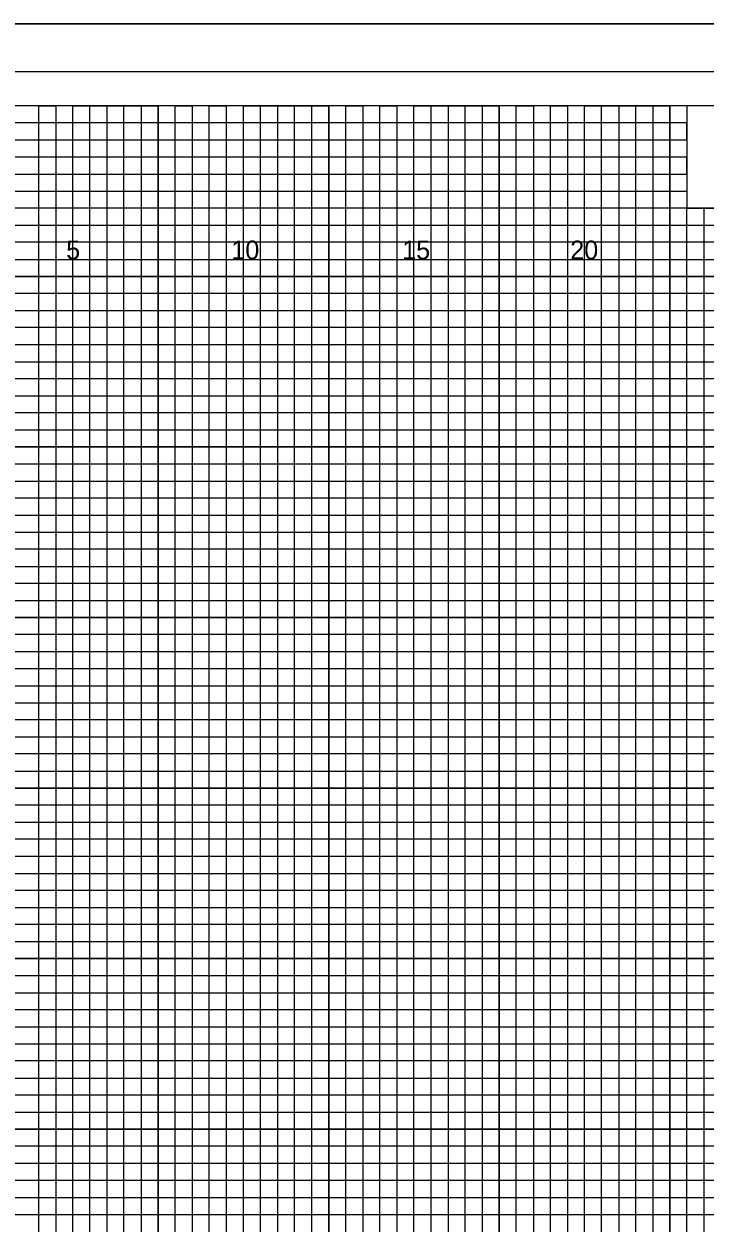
# Model space of a CAD drawing. Extents: x -4 to 103, y -2 to 209.
# Drawn here: x 54.82 to 74.78, y 32.25 to 67.4 of the extents above; entities that cross this region are included whole.
import ezdxf

# ---------------------------------------------------------------- set-up
doc = ezdxf.new("R2010")
doc.units = 0
for name, color, linetype in [('Exist XS Ground Line', 7, 'Continuous'), ('Old_Level_10', 7, 'Continuous'), ('Old_Level_16', 7, 'Continuous'), ('Old_Level_3', 7, 'Continuous'), ('Old_Level_5', 7, 'Continuous'), ('Old_Level_8', 7, 'Continuous'), ('Prop XS Finish Grade Earthwork', 7, 'Continuous'), ('Prop XS SE Text', 7, 'Continuous')]:
    doc.layers.add(name, color=color, linetype=linetype)

msp = doc.modelspace()

# ---------------------------------------------------------------- linework, layer by layer
at = {"layer": 'Exist XS Ground Line'}
msp.add_lwpolyline([(103, 66), (-2.8, 66), (-2.8, -1), (103, -1)], close=True, dxfattribs=at)
at = {"layer": 'Old_Level_10'}
for p, q in [((56.25, 0), (56.25, 65)), ((58.75, 0), (58.75, 65)), ((61.25, 0), (61.25, 65)), ((63.75, 0), (63.75, 65)), ((66.25, 0), (66.25, 65)), ((68.75, 0), (68.75, 65)), ((71.25, 0), (71.25, 65)), ((73.75, 0), (73.75, 65)), ((0, 62.5), (74.25, 62.5)), ((0, 60), (102.5, 60)), ((0, 57.5), (102.5, 57.5)), ((0, 55), (102.5, 55)), ((0, 52.5), (102.5, 52.5)), ((0, 50), (102.5, 50)), ((0, 47.5), (102.5, 47.5)), ((0, 45), (102.5, 45)), ((0, 42.5), (102.5, 42.5)), ((0, 40), (102.5, 40)), ((0, 37.5), (102.5, 37.5)), ((0, 35), (102.5, 35)), ((0, 32.5), (102.5, 32.5))]:
    msp.add_line(p, q, dxfattribs=at)
at = {"layer": 'Old_Level_3'}
msp.add_line((-3.5, 67.4), (103.4, 67.4), dxfattribs=at)
at = {"layer": 'Old_Level_5'}
msp.add_lwpolyline([(103.4, 67.4), (-3.5, 67.4), (-3.5, -2.425), (103.4, -2.425)], close=True, dxfattribs=at)
at = {"layer": 'Old_Level_8'}
for points in [[(56.25, 0), (56.25, 65), (58.75, 65), (58.75, 0)], [(61.25, 0), (61.25, 65), (63.75, 65), (63.75, 0)], [(66.25, 0), (66.25, 65), (68.75, 65), (68.75, 0)], [(71.25, 0), (71.25, 65), (73.75, 65), (73.75, 0)], [(0, 62.5), (74.25, 62.5)], [(0, 57.5), (102.5, 57.5), (102.5, 60), (0, 60)], [(0, 52.5), (102.5, 52.5), (102.5, 55), (0, 55)], [(0, 47.5), (102.5, 47.5), (102.5, 50), (0, 50)], [(0, 42.5), (102.5, 42.5), (102.5, 45), (0, 45)], [(0, 37.5), (102.5, 37.5), (102.5, 40), (0, 40)], [(0, 32.5), (102.5, 32.5), (102.5, 35), (0, 35)]]:
    msp.add_lwpolyline(points, dxfattribs=at)
at = {"layer": 'Prop XS Finish Grade Earthwork'}
for points in [[(55.25, 0), (55.25, 65), (55.75, 65), (55.75, 0)], [(56.75, 0), (56.75, 65), (57.25, 65), (57.25, 0)], [(57.75, 0), (57.75, 65), (58.25, 65), (58.25, 0)], [(59.25, 0), (59.25, 65), (59.75, 65), (59.75, 0)], [(60.25, 0), (60.25, 65), (60.75, 65), (60.75, 0)], [(61.75, 0), (61.75, 65), (62.25, 65), (62.25, 0)], [(62.75, 0), (62.75, 65), (63.25, 65), (63.25, 0)], [(64.25, 0), (64.25, 65), (64.75, 65), (64.75, 0)], [(65.25, 0), (65.25, 65), (65.75, 65), (65.75, 0)], [(66.75, 0), (66.75, 65), (67.25, 65), (67.25, 0)], [(67.75, 0), (67.75, 65), (68.25, 65), (68.25, 0)], [(69.25, 0), (69.25, 65)], [(69.25, 65), (69.75, 65), (69.75, 0)], [(70.25, 0), (70.25, 65), (70.75, 65), (70.75, 0)], [(71.75, 0), (71.75, 65), (72.25, 65), (72.25, 0)], [(72.75, 0), (72.75, 65), (73.25, 65), (73.25, 0)], [(0, 62), (0, 63), (74.25, 63), (74.25, 63.5), (0, 63.5), (0, 64), (74.25, 64), (74.25, 64.5), (0, 64.5)], [(0, 61.5), (102.5, 61.5), (102.5, 62), (0, 62)], [(74.25, 0), (74.25, 62), (74.75, 62), (74.75, 0)], [(0, 60.5), (102.5, 60.5), (102.5, 61), (0, 61)], [(0, 59), (102.5, 59), (102.5, 59.5), (0, 59.5)], [(0, 58), (102.5, 58), (102.5, 58.5), (0, 58.5)], [(0, 56.5), (102.5, 56.5), (102.5, 57), (0, 57)], [(0, 55.5), (102.5, 55.5), (102.5, 56), (0, 56)], [(0, 54), (102.5, 54), (102.5, 54.5), (0, 54.5)], [(0, 53), (102.5, 53), (102.5, 53.5), (0, 53.5)], [(0, 51.5), (102.5, 51.5), (102.5, 52), (0, 52)], [(0, 50.5), (102.5, 50.5), (102.5, 51), (0, 51)], [(0, 49), (102.5, 49), (102.5, 49.5), (0, 49.5)], [(0, 48), (102.5, 48), (102.5, 48.5), (0, 48.5)], [(0, 46.5), (102.5, 46.5), (102.5, 47), (0, 47)], [(0, 45.5), (102.5, 45.5), (102.5, 46), (0, 46)], [(0, 44), (102.5, 44), (102.5, 44.5), (0, 44.5)], [(0, 43), (102.5, 43), (102.5, 43.5), (0, 43.5)], [(0, 41.5), (102.5, 41.5), (102.5, 42), (0, 42)], [(0, 40.5), (102.5, 40.5), (102.5, 41), (0, 41)], [(0, 39), (102.5, 39), (102.5, 39.5), (0, 39.5)], [(0, 38), (102.5, 38), (102.5, 38.5), (0, 38.5)], [(0, 36.5), (102.5, 36.5), (102.5, 37), (0, 37)], [(0, 35.5), (102.5, 35.5), (102.5, 36), (0, 36)], [(0, 34), (102.5, 34), (102.5, 34.5), (0, 34.5)], [(0, 33), (102.5, 33), (102.5, 33.5), (0, 33.5)]]:
    msp.add_lwpolyline(points, dxfattribs=at)
at = {"layer": 'Prop XS SE Text'}
for points in [[(102.5, 65), (0, 65), (0, 0), (102.5, 0)], [(83.75, 65), (74.25, 65), (74.25, 62), (83.75, 62)]]:
    msp.add_lwpolyline(points, close=True, dxfattribs=at)

# ---------------------------------------------------------------- texts
at = {"layer": 'Old_Level_16'}
for s, p in [('5', (56.057, 60.5)), ('10', (60.897, 60.5)), ('15', (65.906, 60.5)), ('20', (70.831, 60.5))]:
    msp.add_text(s, height=0.55, dxfattribs=at).set_placement(p)

doc.saveas('drawing.dxf')
